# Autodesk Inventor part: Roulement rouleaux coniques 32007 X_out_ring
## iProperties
Created: 2000-12
Part Number: Roulement rouleaux coniques 32007 X_out_ring
Material: Par défaut
Document SubType Name: Modélisation
Designer: Administrateur
Control State: 0
Master: False
Checked Out: False
Shininess: 20.0
Length Units: 11269
Angle Units: 11279
Time Units: 11290
Mass Units: 11283
Length Display Precision: 3
Angle Display Precision: 2
Density: 0.0
Volumn: 0.0
Area: 0.0
PropertySet Name: Model Information
Author: Administrateur
